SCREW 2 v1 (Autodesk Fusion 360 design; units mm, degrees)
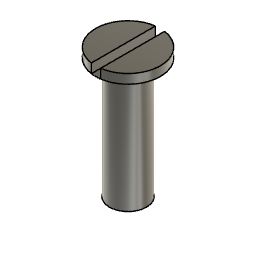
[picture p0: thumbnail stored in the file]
sketch "Sketch1" plane through (0, 0, 0) normal (0, 1, 0) x axis (1, 0, 0)
  line L1 (0, -69.9357) -> (0, 0)
  line L2 (5.25, -22.7321) -> (0, -22.7321)
  line L3 (0, 0) -> (0, -22.7321)
  line L4 (5.25, -21.2321) -> (5.25, -22.7321)
  line L5 (0, 0) -> (3, -1.7321)
  line L6 (-71.0977, 0) -> (0, 0)
  line L7 (3, -1.7321) -> (3, -19.7321)
  line L8 (3, -19.7321) -> (5.25, -21.2321)
  point P3 (0, 0)
  point P4 (0, 0)
  point P7 (0, 0)
  point P11 (0, -22.7321)
  point P6 (0, 0)
  point P2 (0, 0)
  point P1 (0, 0)
  point P8 (3, -19.7321)
  point P12 (3, -1.7321)
  point P5 (5.25, -22.7321)
  point P13 (5.25, -21.2321)
  coincident P3 P4
  coincident P3 P7
  perpendicular L1 L6
  coincident P11 L1
  perpendicular L1 L2
  perpendicular L2 L4
  perpendicular L2 L7
  coincident P3 P6
  coincident P2 P3
  coincident P1 P2
  vertical L1
  dimension "d3" distance L1 L7 = 3
  dimension "d5" angle L3 L5 = 60
  dimension "d12" distance P8 P12 = 18
  dimension "d13" distance P5 P13 = 1.5
  dimension "d14" distance P8 L2 = 3
  dimension "d15" distance L1 L4 = 5.25
revolve "Revolve1" sketch "Sketch1" AlongAngle 360
sketch "Sketch2" plane through (0, 0, 0) normal (0, 1, 0) x axis (1, 0, 0)
  line L1 (0.75, -27.3977) -> (-0.75, -27.3977)
  line L2 (0.75, -21.2321) -> (0.75, -27.3977)
  line L3 (-0.75, -21.2321) -> (0.75, -21.2321)
  line L4 (-0.75, -27.3977) -> (-0.75, -21.2321)
  line L5 (0, -33.7632) -> (0, 0)
  line L6 (5.25, -22.7321) -> (-5.25, -22.7321)
  point P1 (0, 0)
  point P6 (0, 0)
  point P4 (0.75, -21.2321)
  point P5 (-0.75, -21.2321)
  horizontal L1
  vertical L2
  horizontal L3
  vertical L4
  coincident P1 P6
  vertical L5
  symmetric L2 L4 L5
  dimension "d8" distance P4 P5 = 1.5
  dimension "d9" distance L3 L6 = 1.5
extrude "Extrude1" cut sketch "Sketch2" profile of L1 L2 L3 L4 L6 distance 7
